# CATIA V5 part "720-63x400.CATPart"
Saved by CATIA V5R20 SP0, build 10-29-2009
Part number: 720-63x400
Definition: NONE
Nomenclature: 720-63x400
Source: Unknown
Description: 720-63x400
Bounding box of the stored display mesh (mm): x 0 to 400, y -31.5 to 31.5, z -31.5 to 31.5
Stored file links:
  C:\Users\Utente\Desktop\IO LAVORO\3D X SITO CF\X SITO\720\720-63x400.CATPart

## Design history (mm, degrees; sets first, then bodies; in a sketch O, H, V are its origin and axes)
Body1 "720-63x400" (main body)
  Solid1: solid without history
